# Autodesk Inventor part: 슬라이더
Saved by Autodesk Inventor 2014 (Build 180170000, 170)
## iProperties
Created: 2026-06
Part Number: 슬라이더
Material: 일반
Document SubType Name: Modeling
Designer: dg
Density: 1 g/cm^3
Appearance: 기본값
Author: dg
Author: jhkim
Creation Date: 2026-05-29
Sending System: Autodesk Inventor 2027
Preprocessor: ST-DEVELOPER v20.1
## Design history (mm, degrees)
node "슬라이더1"
node "솔리드1"
node "기준1"
